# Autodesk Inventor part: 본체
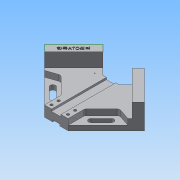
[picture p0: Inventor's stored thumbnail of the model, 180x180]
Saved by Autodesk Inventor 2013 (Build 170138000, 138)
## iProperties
Created: 2019-04
Part Number: 본체
Material: 알루미늄 6061
Document SubType Name: Modeling
Designer: Administrator
Density: 2.71 g/cm^3
Mass: 603.686 g
Surface Area: 426.594 cm^2
Volume: 222.762 cm^3
Author: Administrator
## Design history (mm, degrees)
sketch "스케치1"
  geometry: L1 (0, 84.853)-(0, -84.853); L2 (-35.355, 49.497)-(-84.853, 0); L3 (-84.853, 0)-(-20, -64.853); L4 (-20, -64.853)-(0, -64.853); L5 (-35.355, 49.497)-(-14.005, 28.147); L6 (-35.355, 49.497)-(-69.687, 83.829); L7 (0, 28.147)-(-14.005, 28.147); L8 (35.355, 49.497)-(84.853, 0); L9 (35.355, 49.497)-(14.005, 28.147); L10 (0, 28.147)-(14.005, 28.147); L11 (84.853, 0)-(20, -64.853); L12 (20, -64.853)-(0, -64.853); 2 further points
  constraints: 24 end point, 4 symmetric about line, 2 parallel, 2 point on line, 1 coincident, 1 collinear, 1 midpoint, 1 perpendicular, 1 vertical
  dimensions: "d0" = 90 deg angle of L3 L2; "d1" = 120 distance of L1.start L2.end; "d3" = 120 distance of L2.end L1.end; "d4" = 20 distance of L1.end L4.end; "d6" = 50 distance from line of L1.start L6; "d7" = 93 distance of L4.end L7.start
extrude "돌출1" new body sketch "스케치1" distance "d8" = 18; taper "d9" = 0 deg
sketch "스케치2"
  geometry: L1 (-14.005, 28.147)-(-35.355, 49.497) reference; L2 (-35.355, 49.497)-(-84.853, 0) reference; L3 (-84.853, 0)-(-20, -64.853) reference; L4 (-24.749, 38.891)-(-74.246, -10.607); 1 further point
  constraints: 2 end point, 2 point on line, 1 perpendicular
extrude "돌출2" join sketch "스케치2" distance "d12" = 24; taper "d13" = 0 deg
sketch "스케치3"
  geometry: L1 (14.005, 28.147)-(-14.005, 28.147) reference; L2 (-20, -64.853)-(20, -64.853) reference; L3 (-8, 28.147)-(8, 28.147); L4 (8, 28.147)-(8, -64.853); L5 (8, -64.853)-(-8, -64.853); L6 (-8, -64.853)-(-8, 28.147); 2 further points
  constraints: 8 end point, 2 parallel, 2 point on line, 1 horizontal, 1 midpoint, 1 perpendicular, 1 vertical alignment
  dimensions: "d14" = 16 distance of L3.start L3.end
extrude "돌출3" cut sketch "스케치3" distance "d16" = 3.5; taper "d17" = 0 deg
sketch "스케치4"
  geometry: L1 (20, -64.853)-(-20, -64.853) reference; L2 (-14.005, 28.147)-(14.005, 28.147) reference; L3 (-6, 28.147)-(6, 28.147); L4 (6, 28.147)-(6, -64.853); L5 (6, -64.853)-(-6, -64.853); L6 (-6, -64.853)-(-6, 28.147); 2 further points
  constraints: 8 end point, 2 parallel, 2 point on line, 1 horizontal, 1 midpoint, 1 perpendicular, 1 vertical alignment
  dimensions: "d18" = 12 distance of L3.start L3.end
extrude "돌출4" cut sketch "스케치4" distance "d20" = 3; taper "d21" = 0 deg
sketch "스케치5"
  geometry: L1 (-74.246, -10.607)-(-20, -64.853) reference; L2 (-20, -64.853)-(-8, -64.853) reference; L3 (-70.711, -14.142)-(-49.497, -7.071); L4 (-20, -64.853)-(-20, -36.569); L5 (-20, -36.569)-(-49.497, -7.071); L6 (-35.355, 49.497)-(-84.853, 0) reference; 1 further point
  constraints: 6 end point, 1 parallel, 1 perpendicular, 1 point on line
  dimensions: "d22" = 20 distance from line of L3.start L6; "d23" = 20 distance from line of L1 L3.end; "d24" = 30 distance from line of L6 L3.end
extrude "돌출5" cut sketch "스케치5" distance "d25" = 10; taper "d26" = 0 deg
sketch "스케치6"
  geometry: L1 (-20, -64.853)-(-70.711, -14.142) reference; L2 (-35.355, 49.497)-(-84.853, 0) reference; L3 (-52.593, -24.479)-(-35.709, -41.366); L4 (-46.231, -18.118)-(-29.345, -35.002); A1 r 4.5 centre (-49.497, -21.213) between (-46.231, -18.118) and (-52.593, -24.479); A2 r 4.5 centre (-32.527, -38.184) between (-35.709, -41.366) and (-29.345, -35.002); 1 further point
  constraints: 4 end point, 4 point on circle, 2 centre point, 2 tangent
  dimensions: "d27" = 9 diameter of A1; "d28" = 40 distance from line of A1.centre L2; "d29" = 10 distance from line of L1 A1.centre; "d32" = 9 diameter of A2
extrude "돌출6" cut sketch "스케치6" stored distance "d33" = 10; taper "d34" = 0 deg
sketch "스케치7"
  geometry: L1 (-20, -64.853)-(-8, -64.853) reference; C1 r 2.25 at (-14, -58.853); C2 r 2.25 at (-14, -46.853); 1 further point
  constraints: 2 centre point
  dimensions: "d35" = 4.5 diameter of C1; "d36" = 14 horizontal distance of point (0, 0) C1.centre; "d37" = 6 distance from line of L1 C1.centre; "d38" = 4.5 diameter of C2; "d39" = 12 distance of C1.centre C2.centre
extrude "돌출7" cut sketch "스케치7" stored distance "d40" = 10; taper "d41" = 0 deg
sketch "스케치8"
  geometry: C1 r 2.25 at (14, -58.853) reference; C2 r 2.25 at (14, -46.853) reference; C3 r 4 at (14, -58.853); C4 r 4 at (14, -46.853); 1 further point
  constraints: 2 centre point, 2 coincident
  dimensions: "d42" = 8 diameter of C3; "d43" = 8 diameter of C4
extrude "돌출8" cut sketch "스케치8" distance "d44" = 10; taper "d45" = 0 deg
fillet "모깎기1" dims "d47" = 5
sketch "스케치13"
  geometry: L1 (-35.355, 49.497)-(-84.853, 0) reference; L2 (-84.853, 0)-(-74.246, -10.607) reference; L3 (-74.246, -10.607)-(-24.749, 38.891) reference; L4 (-24.749, 38.891)-(-35.355, 49.497) reference; 1 further point
node "작업 평면2"
sketch "스케치14"
  geometry: L1 (-66.62, 2.035)-(-36.524, 32.745); 1 further point
  constraints: 2 end point, 1 other
feature "엠보싱1" sketch "스케치14" dims "d0" = 90 deg, "d1" = 120, "d3" = 120, "d4" = 20, "d6" = 50, "d7" = 93, "d49" = 0.5, "d50" = 0
node "솔리드1"
mirror "대칭1"
mirror "대칭2"
other parameters: "d48" = 183.25
